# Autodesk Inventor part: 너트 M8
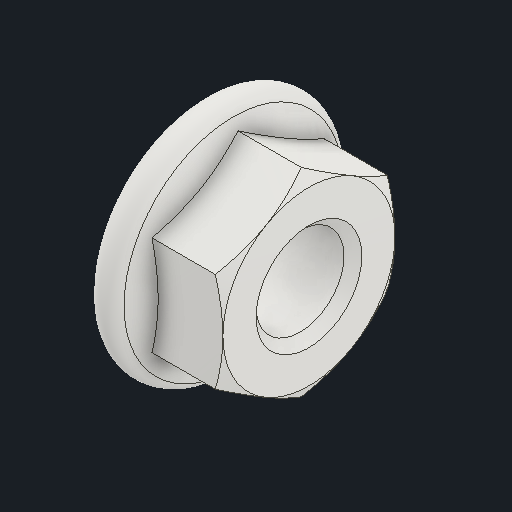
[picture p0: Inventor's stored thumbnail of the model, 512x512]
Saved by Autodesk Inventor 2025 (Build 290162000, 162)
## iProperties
Created: 2025-08
Part Number: 너트 M8
Material: 스테인리스강
Description: 플랜지붙이 6각 너트 - 일반 스레드
Document SubType Name: Modeling
Designer: infra10
Density: 8 g/cm^3
Appearance: 기본값
Author: jhkim
Sending System: Autodesk Inventor 2026
Preprocessor: ST-DEVELOPER v20.1
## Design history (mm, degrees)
feature "Solid1"
node "솔리드1"
